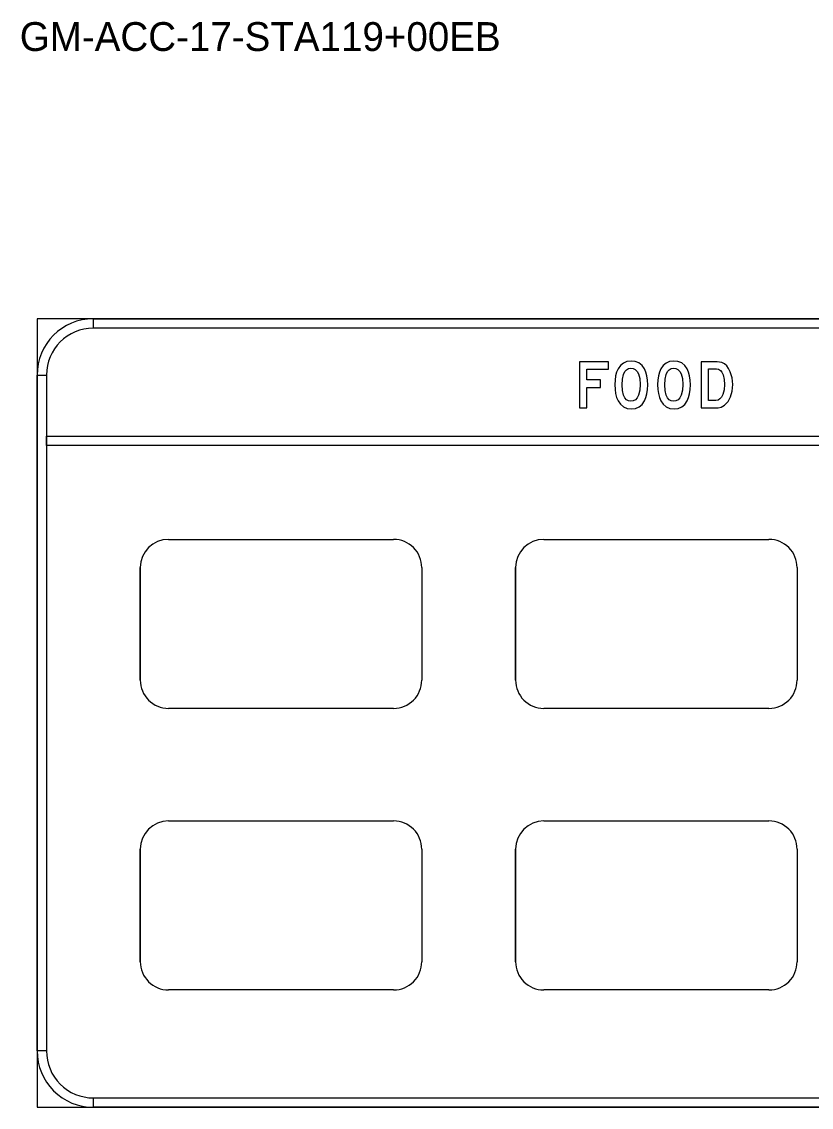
# Model space of a CAD drawing. Extents: x 620861 to 621178, y 415479 to 415559.
# Drawn here: x 620860.61 to 620867.63, y 415529.7 to 415539.34 of the extents above; entities that cross this region are included whole.
import ezdxf

# ---------------------------------------------------------------- set-up
doc = ezdxf.new("R2010")
doc.units = 0
doc.layers.add('SIGNS', color=7, linetype='Continuous')

msp = doc.modelspace()

# ---------------------------------------------------------------- linework, layer by layer
at = {"layer": 'SIGNS'}
for p, q in [((620871.7509, 415536.6995), (620860.7509, 415536.6995)), ((620860.7509, 415536.6995), (620860.7509, 415529.6995)), ((620861.2509, 415536.6162), (620861.2509, 415536.6995)), ((620860.7509, 415536.1995), (620860.8343, 415536.1995)), ((620861.9176, 415534.7412), (620863.9176, 415534.7412)), ((620865.2509, 415534.7412), (620867.2509, 415534.7412)), ((620861.6676, 415534.4912), (620861.6676, 415533.4912)), ((620861.6676, 415533.4912), (620861.6676, 415534.4912)), ((620864.1676, 415534.4912), (620864.1676, 415533.4912)), ((620865.0009, 415534.4912), (620865.0009, 415533.4912)), ((620865.0009, 415533.4912), (620865.0009, 415534.4912)), ((620867.5009, 415534.4912), (620867.5009, 415533.4912)), ((620863.9176, 415533.2412), (620861.9176, 415533.2412)), ((620861.9176, 415533.2412), (620861.9176, 415533.2412)), ((620867.2509, 415533.2412), (620865.2509, 415533.2412)), ((620865.2509, 415533.2412), (620865.2509, 415533.2412)), ((620861.9176, 415532.2412), (620863.9176, 415532.2412)), ((620865.2509, 415532.2412), (620867.2509, 415532.2412)), ((620861.6676, 415531.9912), (620861.6676, 415530.9912)), ((620861.6676, 415530.9912), (620861.6676, 415531.9912)), ((620864.1676, 415531.9912), (620864.1676, 415530.9912)), ((620865.0009, 415531.9912), (620865.0009, 415530.9912)), ((620865.0009, 415530.9912), (620865.0009, 415531.9912)), ((620867.5009, 415531.9912), (620867.5009, 415530.9912)), ((620863.9176, 415530.7412), (620861.9176, 415530.7412)), ((620861.9176, 415530.7412), (620861.9176, 415530.7412)), ((620867.2509, 415530.7412), (620865.2509, 415530.7412)), ((620865.2509, 415530.7412), (620865.2509, 415530.7412)), ((620860.8343, 415530.1995), (620860.7509, 415530.1995)), ((620861.2509, 415529.6995), (620861.2509, 415529.7829)), ((620860.7509, 415529.6995), (620871.7509, 415529.6995)), ((620860.7509, 415529.6995), (620860.7509, 415529.6995)), ((620860.7509, 415529.6995), (620860.7509, 415529.6995))]:
    msp.add_line(p, q, dxfattribs=at)
for points in [[(620871.2509, 415536.6162), (620861.2509, 415536.6162), (620861.2509, 415536.6995), (620871.2509, 415536.6995), (620871.2509, 415536.6162), (620871.2509, 415536.6162)], [(620865.5697, 415535.9079), (620865.6335, 415535.9079), (620865.6335, 415536.0884), (620865.7538, 415536.0884), (620865.7538, 415536.1562), (620865.6335, 415536.1562), (620865.6335, 415536.2524), (620865.8252, 415536.2524), (620865.8252, 415536.3165), (620865.5697, 415536.3165)], [(620860.8343, 415536.1995), (620860.8343, 415530.1995), (620860.7509, 415530.1995), (620860.7509, 415536.1995), (620860.8343, 415536.1995), (620860.8343, 415536.1995)], [(620860.8343, 415535.6579), (620871.6676, 415535.6579), (620871.6676, 415535.5745), (620860.8343, 415535.5745), (620860.8343, 415535.6579), (620860.8343, 415535.6579)], [(620861.2509, 415529.7829), (620871.2509, 415529.7829), (620871.2509, 415529.6995), (620861.2509, 415529.6995), (620861.2509, 415529.7829), (620861.2509, 415529.7829)]]:
    msp.add_lwpolyline(points, close=True, dxfattribs=at)
for points in [[(620866.1747, 415536.1124), (620866.1729, 415536.1551), (620866.1672, 415536.1933), (620866.158, 415536.2269), (620866.1451, 415536.256), (620866.1235, 415536.2858), (620866.0965, 415536.3073), (620866.064, 415536.3201), (620866.026, 415536.3245), (620865.9893, 415536.3201), (620865.958, 415536.307), (620865.9319, 415536.2851), (620865.911, 415536.2544), (620865.8983, 415536.2252), (620865.8893, 415536.1924), (620865.8839, 415536.1556), (620865.8822, 415536.1152), (620865.8839, 415536.0731), (620865.8893, 415536.0353), (620865.8983, 415536.0016), (620865.911, 415535.9721), (620865.9322, 415535.9404), (620865.959, 415535.9178), (620865.9913, 415535.9044), (620866.0293, 415535.8999), (620866.0658, 415535.9043), (620866.0974, 415535.9176), (620866.1239, 415535.9399), (620866.1454, 415535.9712), (620866.1582, 415536.0008), (620866.1674, 415536.0344), (620866.1729, 415536.0715), (620866.1747, 415536.1124)], [(620866.1065, 415536.1172), (620866.1029, 415536.0646), (620866.0921, 415536.0216), (620866.08, 415535.9976), (620866.0646, 415535.9804), (620866.0459, 415535.9702), (620866.0241, 415535.9668), (620866.0032, 415535.9702), (620865.9856, 415535.9804), (620865.971, 415535.9976), (620865.9598, 415536.0216), (620865.9496, 415536.0633), (620865.9463, 415536.1139), (620865.9496, 415536.1638), (620865.9598, 415536.2057), (620865.9709, 415536.2302), (620865.9852, 415536.2478), (620866.0024, 415536.2583), (620866.0225, 415536.2618), (620866.0447, 415536.2585), (620866.0637, 415536.249), (620866.0793, 415536.233), (620866.0917, 415536.2107), (620866.1028, 415536.1691), (620866.1065, 415536.1172)], [(620866.5539, 415536.1124), (620866.552, 415536.1551), (620866.5464, 415536.1933), (620866.5371, 415536.2269), (620866.5243, 415536.256), (620866.5027, 415536.2858), (620866.4757, 415536.3073), (620866.4431, 415536.3201), (620866.4052, 415536.3245), (620866.3685, 415536.3201), (620866.3372, 415536.307), (620866.311, 415536.2851), (620866.2901, 415536.2544), (620866.2775, 415536.2252), (620866.2685, 415536.1924), (620866.2631, 415536.1556), (620866.2613, 415536.1152), (620866.2631, 415536.0731), (620866.2685, 415536.0353), (620866.2775, 415536.0016), (620866.2901, 415535.9721), (620866.3114, 415535.9404), (620866.3382, 415535.9178), (620866.3705, 415535.9044), (620866.4084, 415535.8999), (620866.445, 415535.9043), (620866.4765, 415535.9176), (620866.5031, 415535.9399), (620866.5246, 415535.9712), (620866.5374, 415536.0008), (620866.5465, 415536.0344), (620866.552, 415536.0715), (620866.5539, 415536.1124)], [(620866.4857, 415536.1172), (620866.482, 415536.0646), (620866.4713, 415536.0216), (620866.4592, 415535.9976), (620866.4437, 415535.9804), (620866.4251, 415535.9702), (620866.4033, 415535.9668), (620866.3824, 415535.9702), (620866.3648, 415535.9804), (620866.3502, 415535.9976), (620866.339, 415536.0216), (620866.3288, 415536.0633), (620866.3254, 415536.1139), (620866.3288, 415536.1638), (620866.339, 415536.2057), (620866.3501, 415536.2302), (620866.3643, 415536.2478), (620866.3815, 415536.2583), (620866.4017, 415536.2618), (620866.4239, 415536.2585), (620866.4429, 415536.249), (620866.4585, 415536.233), (620866.4709, 415536.2107), (620866.4819, 415536.1691), (620866.4857, 415536.1172)], [(620866.7922, 415536.3165), (620866.6488, 415536.3165), (620866.6488, 415535.9079), (620866.7988, 415535.9079), (620866.8263, 415535.914), (620866.856, 415535.9324), (620866.8879, 415535.9657), (620866.9107, 415536.0078), (620866.9244, 415536.0583), (620866.929, 415536.1174), (620866.9237, 415536.1748), (620866.9076, 415536.2295), (620866.893, 415536.2588), (620866.8758, 415536.2822), (620866.8559, 415536.2995), (620866.8334, 415536.3107), (620866.7922, 415536.3165)], [(620866.7793, 415535.9751), (620866.7129, 415535.9751), (620866.7129, 415536.2553), (620866.7853, 415536.2553), (620866.8036, 415536.2519), (620866.8196, 415536.242), (620866.8329, 415536.2254), (620866.8438, 415536.2026), (620866.8538, 415536.1619), (620866.8572, 415536.1152), (620866.8533, 415536.0678), (620866.8418, 415536.0265), (620866.8301, 415536.0039), (620866.8158, 415535.9878), (620866.7988, 415535.9782), (620866.7793, 415535.9751)]]:
    msp.add_lwpolyline(points, dxfattribs=at)
for centre, radius, start, end in [((620861.2509, 415536.1995), 0.5, 90.00021, 179.99985), ((620861.2509, 415536.1995), 0.4167, 90.00021, 179.99985), ((620861.9176, 415534.4912), 0.25, 90.00021, 179.99985), ((620863.9176, 415534.4912), 0.25, 0, 90.00021), ((620865.2509, 415534.4912), 0.25, 90.00021, 179.99985), ((620867.2509, 415534.4912), 0.25, 0, 90.00021), ((620861.9176, 415533.4912), 0.25, 179.99985, 270.00006), ((620863.9176, 415533.4912), 0.25, 270.00006, 0.00027), ((620865.2509, 415533.4912), 0.25, 179.99985, 270.00006), ((620867.2509, 415533.4912), 0.25, 270.00006, 0.00027), ((620861.9176, 415531.9912), 0.25, 90.00021, 179.99985), ((620863.9176, 415531.9912), 0.25, 0, 90.00021), ((620865.2509, 415531.9912), 0.25, 90.00021, 179.99985), ((620867.2509, 415531.9912), 0.25, 0, 90.00021), ((620861.9176, 415530.9912), 0.25, 179.99985, 270.00006), ((620863.9176, 415530.9912), 0.25, 270.00006, 0.00027), ((620865.2509, 415530.9912), 0.25, 179.99985, 270.00006), ((620867.2509, 415530.9912), 0.25, 270.00006, 0.00027), ((620861.2509, 415530.1995), 0.5, 179.99985, 270.00006), ((620861.2509, 415530.1995), 0.4167, 179.99985, 270.00006)]:
    msp.add_arc(centre, radius, start, end, dxfattribs=at)

# ---------------------------------------------------------------- texts
msp.add_text('GM-ACC-17-STA119+00EB', height=0.256, dxfattribs=at).set_placement((620860.597, 415539.0772))

doc.saveas('drawing.dxf')
